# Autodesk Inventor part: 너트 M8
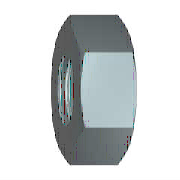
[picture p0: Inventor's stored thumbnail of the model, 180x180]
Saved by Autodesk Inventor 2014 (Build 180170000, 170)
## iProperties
IsCustomPart: 1
Created: 2012-02
Part Number: 너트 M8
Material: 강철, 연강
Description: 6각 너트 및 6각 가는 너트 - 이중 모따기
Document SubType Name: Modeling
Standard: KS B 1012
Designer: mduedu
Standards Organization: KS
Language: ko-KR
Size Designation: A M8
Categories: <MemberInstance><Categories><Category DisplayName="조임쇠" InternalName="e4da775c-781d-43d5-af7c-5136215cf5a6" Mnemonic="FSTN"><Category DisplayName="너트" InternalN
Density: 7.86 g/cm^3
Mass: 3.42669 g
Surface Area: 4.61759 cm^2
Volume: 0.435966 cm^3
Appearance: 강철
Author: mduedu
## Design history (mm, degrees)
sketch "스케치1"
  geometry: L1 (-7.506, 0)-(-3.753, 6.5); L2 (-3.753, 6.5)-(3.753, 6.5); L3 (3.753, 6.5)-(7.506, 0); L4 (7.506, 0)-(3.753, -6.5); L5 (3.753, -6.5)-(-3.753, -6.5); L6 (-3.753, -6.5)-(-7.506, 0); 2 further points
  constraints: 12 end point, 1 coincident, 1 horizontal, 11 other
  dimensions: "d0" = 15.01111 distance of L3.end L1.start (= 1.1547 x SW)
extrude "본체" new body sketch "스케치1" distance "d1" = 4 (= KOH); taper "d2" = 0 deg
sketch "스케치2"
  geometry: L1 (0, 3.753)-(0, 7.506) reference; L2 (0, 7.506)-(4, 7.506) reference; L3 (4, 3.753)-(4, 7.506) reference; L4 (-0.8, 0)-(4.8, 0) reference; L5 (0.581, 7.506)-(0, 6.5); L6 (3.419, 7.506)-(4, 6.5)
  constraints: 4 end point, 4 point on line
  dimensions: "d3" = 30 deg angle of L1 L5 (= ANG1); "d4" = 30 deg angle of L3 L6 (= ANG2); "d5" = 13 diameter of L5.end L4 (= SW0); "d6" = 13 diameter of L6.end L4 (= SW01)
revolve "모따기1" sketch "스케치2" stored, may be unused: angle "d7" = 90 deg
sketch "스케치3"
  geometry: A1 r 6.5 centre (0, 0) between (-3.25, -5.629) and (3.25, -5.629) reference; 1 further point
  constraints: 1 coincident
hole "스레드" sketch "스케치3" at (0, 0) diameter "d25" = 6.647; stored, may be unused: countersink angle "d29" = 82 deg, drill point angle "d31" = 118 deg; dims "d26" = 6, "d27" = 4, "d28" = 2, "d30" = 8
workaxis "Work Axis1"
workplane "Work Plane1"
body "Solid1"
chamfer "모따기2" distance "d8" = 0.67658 (= -0.5 x GD1 + 0.5 x NND); stored, may be unused: angle "d9" = 30 deg, second distance "d40" = 0.67658 (= -0.5 x GD1 + 0.5 x NND)
chamfer "모따기3" distance "d10" = 0.67658 (= -0.5 x GD1 + 0.5 x NND); stored, may be unused: angle "d11" = 30 deg, second distance "d41" = 0.67658 (= -0.5 x GD1 + 0.5 x NND)
other parameters: "ANG1" = 30 deg [user parameter; used in 1 equation term], "ANG2" = 30 deg [user parameter; used in 1 equation term], "NND" = 8 [user parameter; used in 4 equation terms], "KOH" = 4 [user parameter; used in 1 equation term], "SW" = 13 [user parameter; used in 4 equation terms], "SW0" = 13 (= SW) [user parameter; used in 1 equation term], "SW01" = 13 (= SW) [user parameter; used in 1 equation term], "GD1" = 6.64684 (computed from THREADDIA, PTC, TOA) [user parameter; used in 4 equation terms], "d13" = 0, "d14" = 0, "d39" = 0, "d42" = 0, "GUL" = 0.67658 (= 0.541266 x PTC) [user parameter], "TPU" = 8 (computed from PTC) [user parameter], "THREADDIA" = 8 [user parameter; used in 1 equation term], "TOA" = 30 deg [user parameter; used in 1 equation term], "PTC" = 1.25 [user parameter; used in 4 equation terms], "E0" = 15.015 (= 1.155 x SW) [user parameter], "GAL" = 0.67658 (= 0.541266 x PTC) [user parameter]
